(* Logix 5000 project; controller MVI56ESIE vendor 1 type 14 code 51 rev 15.5; software revision 15.02 *)

TASK MainTask (continuous, watchdog 500 ms) : MainProgram

MODULES
   Local : vendor 1 type 14 code 51 (ICP 0, rev 15.5)
      ENBT : 1756-ENBT (Ethernet 105.102.0.13, ICP 6, rev 4.3)
      MVI56ESIE : vendor 1 type 0 code 15 (ICP 1, rev 1.1, Output RPI 5 ms)
END_MODULES

TYPE SIEBLOCKSTATS :   // This object is used to store the block transfer statistics for the MVI56E-SIE module.
STRUCT
   Read : INT;   // Total number of read block transfers
   Write : INT;   // Total number of write block transfers
   Parse : INT;   // Total number of blocks parsed
   Reserved : INT;   // Used internally for future use
   Cmd : INT;   // Total number of command blocks received
   Err : INT;   // Total number of block transfer errors
END_STRUCT
END_TYPE

TYPE SIECLIENTSTATS :   // This object is used to store the port statistics for an MVI56E-SIE port.
STRUCT
   CmdReq : INT;   // Total number of command list requests sent
   CmdResp : INT;   // Total number of command list responses received
   CmdErr : INT;   // Total number of command list errors
   Requests : INT;   // Total number of requests for port
   Responses : INT;   // Total number of responses for port
   ErrSent : INT;   // Total number of errors sent
   ErrRec : INT;   // Total number of errors received
   CfgErrWord : INT;   // Configuration Error Word
   CurErr : INT;   // Current Error code
   LastErr : INT;   // Last recorded error code
END_STRUCT
END_TYPE

TYPE SIECMDCONTROL :   // MVI56E-SIE Command Control
STRUCT
   ClientID : INT;   // Block5000 Client Identification by Index number 0 to 19
   CMDqty : INT;   // Block5000 command quantity
   CmdIndex : INT[16];   // Contains index in the command list for the 1st command to be entered into Command queue
   WriteCmdBits : INT[20];   // Command Bit control ClientID(0 to 19)
END_STRUCT
END_TYPE

TYPE SIECONTROL :   // Values used by program for data transfer operation between the module and the processor.
STRUCT
   BootTimer : TIMER;   // Timer used to clear both cold and warm boot requests
   ColdBoot : BOOL;   // Hardware reset of the Module
   WarmBoot : BOOL;   // Configuration data reset in the Module.
   ResetStatus : BOOL;   // Resets module status
   CmdID : INT;   // Command ID from 1 to 16
   CmdControl : SIECMDCONTROL;   // Holds Command Control statistics
   CmdControlPending : BOOL;   // Halts rung until Module is ready.
   CmdControlTrigger : BOOL;   // Command Control Trigger
   IPAddress : SIEIPADDRESS;   // Getting and Setting IP address to and from Module
END_STRUCT
END_TYPE

TYPE SIEDATA :   // Contains Read Data (data read from the module to the processor) and Write Data (data written from the processor to the module)
STRUCT
   ReadData : INT[600];   // Data read from module. Set array equal to the size set in the Configuration file.
   WriteData : INT[600];   // Data to write to module. Set array equal to the size set in the Configuration file.
END_STRUCT
END_TYPE

TYPE SIEINITOUTDATA :   // Used to bring the Module into a known state after a restart operation.
STRUCT
   InitOutBlkIDLim : INT;   // Block Index Limit for ReadData size of the array
END_STRUCT
END_TYPE

TYPE SIEIPADDRESS :   // Data structure to get and set the IP address of the module.
STRUCT
   IPGetTrigger : BOOL;   // Gets IP Address
   IPReceived : INT[4];   // IP address received.
   IPSetTrigger : BOOL;   // Sets IP Address
   IPRequested : INT[4];   // IP address set.
END_STRUCT
END_TYPE

TYPE SIEMODULEDEF :   // This defines the whole module which includes all tags used in the program
STRUCT
   DATA : SIEDATA;   // Data read from module
   CONTROL : SIECONTROL;   // Client ,Server Status and blocks status
   STATUS : SIESTATUS;   // SIE Module control
   UTIL : SIEUTIL;   // Block statistics
END_STRUCT
END_TYPE

TYPE SIESTATUS :   // This status data is returned on each read block and can be used to detect proper module operation.
STRUCT
   PassCnt : INT;   // Program cycle counter
   ProductVersion : INT;   // This is used to pass the product version to the processor
   ProductCode : INT[2];   // This is used to pass the product Code to the processor
   BlockStats : SIEBLOCKSTATS;   // Block transfer statistics
   CmdBits : INT[20];   // Commands bits array to be used for 30 clients
   ClientStatsTrigger : BOOL;   // Get Client Status
   ClientID : INT;   // Client ID to get Status From
   ClientStatus : SIECLIENTSTATS[20];   // Client status data
   CmdErrorList : INT[16];   // Command Error List
END_STRUCT
END_TYPE

TYPE SIEUTIL :   // Values used by program for data transfer operation between the module and the processor.
STRUCT
   LastRead : INT;   // Index of last read block
   LastWrite : INT;   // Index of last write block
   BlockIndex : INT;   // Computed block offset for data table
   StatusIndex : INT;   // Computed block offset for status data
   ReadDataSizeGet : INT;   // Gets ReadData Array Length.
   WriteDataSizeGet : INT;   // Gets WriteData Array Length.
   ReadDataBlkCount : INT;   // Holds the value of the Block Counts of the Read Data Array.
   WriteDataBlkCount : INT;   // Holds the value of the Block Counts of the Write Data Array.
   RBTSremainder : INT;   // Holds remainder calculation value from the read array.
   WBTSremainder : INT;   // Holds remainder calculation value from the write array.
   IPsetPending : BOOL;   // Allows Setting module IP address
   IPgetPending : BOOL;   // Allows Getting module IP address
   InitOutputData : SIEINITOUTDATA;
   CheckInitialization : BOOL;   // Check Initialization trigger
   StatusSeqIndex : INT;   // Computed block offset for status data
END_STRUCT
END_TYPE

VAR_GLOBAL   (* controller tags *)
   MJFAULTS : DINT[12];
   SIE : SIEMODULEDEF;
END_VAR

PROGRAM MainProgram   (* main routine MainRoutine *)

ROUTINE MainRoutine   (* ladder *)
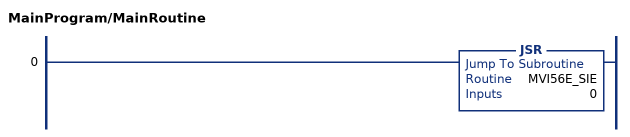
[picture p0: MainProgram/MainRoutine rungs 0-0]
   0: JSR(MVI56E_SIE,0);
END_ROUTINE

ROUTINE MVI56E_SIE   (* ladder *)
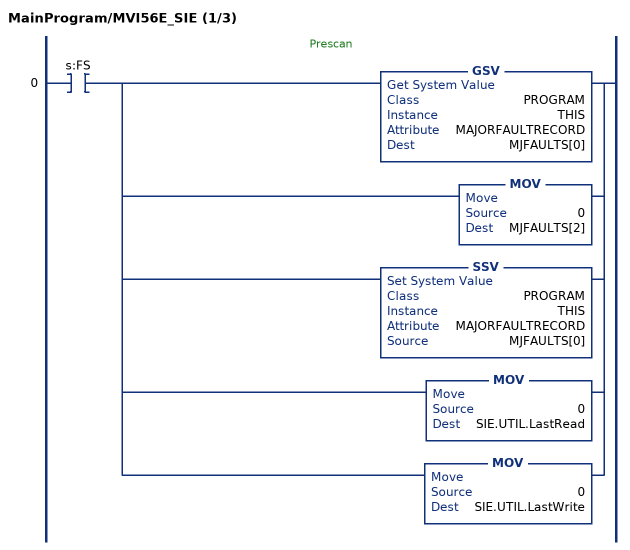
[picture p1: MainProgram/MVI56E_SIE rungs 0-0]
   // Prescan
   0: XIC(s:FS)[[GSV(PROGRAM,THIS,MAJORFAULTRECORD,MJFAULTS[0]) ,MOV(0,MJFAULTS[2]) ,SSV(PROGRAM,THIS,MAJORFAULTRECORD,MJFAULTS[0]) ] ,[MOV(0,SIE.UTIL.LastRead) ,MOV(0,SIE.UTIL.LastWrite) ] ];
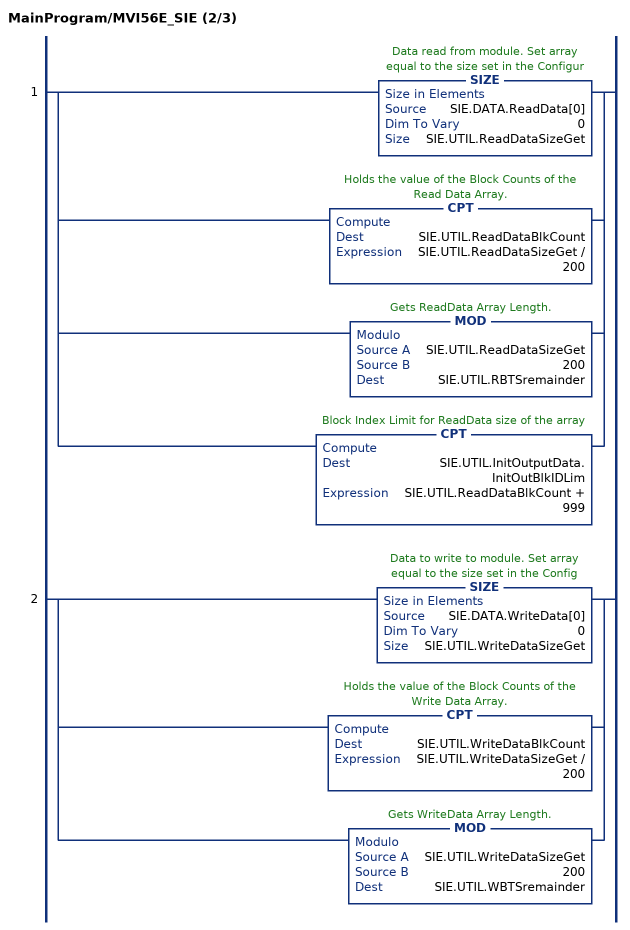
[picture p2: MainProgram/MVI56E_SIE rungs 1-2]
   1: [SIZE(SIE.DATA.ReadData[0],0,SIE.UTIL.ReadDataSizeGet) ,CPT(SIE.UTIL.ReadDataBlkCount,SIE.UTIL.ReadDataSizeGet / 200) ,MOD(SIE.UTIL.ReadDataSizeGet,200,SIE.UTIL.RBTSremainder) ,CPT(SIE.UTIL.InitOutputData.InitOutBlkIDLim,SIE.UTIL.ReadDataBlkCount + 999) ];
   2: [SIZE(SIE.DATA.WriteData[0],0,SIE.UTIL.WriteDataSizeGet) ,CPT(SIE.UTIL.WriteDataBlkCount,SIE.UTIL.WriteDataSizeGet / 200) ,MOD(SIE.UTIL.WriteDataSizeGet,200,SIE.UTIL.WBTSremainder) ];
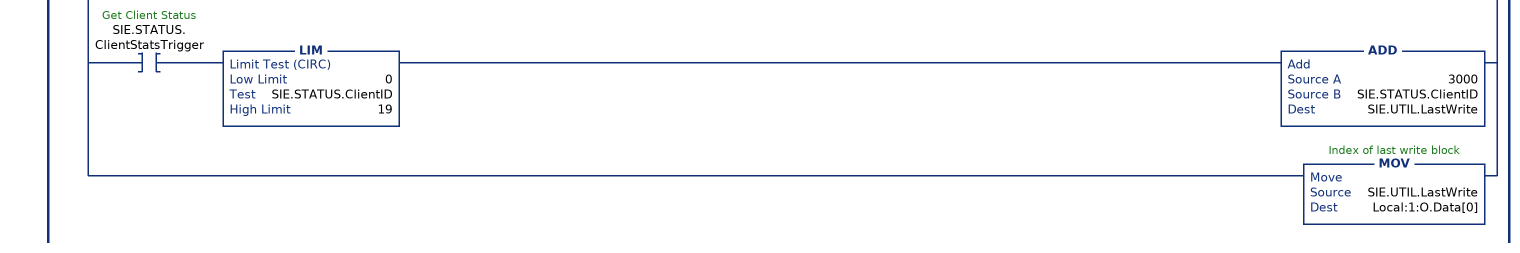
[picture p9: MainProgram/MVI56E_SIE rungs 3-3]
   3: NEQ(Local:1:I.Data[249],SIE.UTIL.LastRead)[MOV(Local:1:I.Data[249],SIE.UTIL.LastRead) ,GEQ(SIE.UTIL.LastRead,1) [LEQ(SIE.UTIL.LastRead,SIE.UTIL.ReadDataBlkCount) [CPT(SIE.UTIL.BlockIndex,(SIE.UTIL.LastRead-1)*200) ,COP(Local:1:I.Data[2],SIE.DATA.ReadData[SIE.UTIL.BlockIndex],200) ,COP(Local:1:I.Data[202],SIE.STATUS.PassCnt,1) ,COP(Local:1:I.Data[203],SIE.STATUS.BlockStats.Read,6) ,COP(Local:1:I.Data[209],SIE.STATUS.CmdBits[0],20) ,COP(Local:1:I.Data[229],SIE.STATUS.ProductCode[0],2) ,COP(Local:1:I.Data[231],SIE.STATUS.ProductVersion,1) ] ,CMP(SIE.UTIL.LastRead - SIE.UTIL.ReadDataBlkCount = 1) GRT(SIE.UTIL.RBTSremainder,0) [CPT(SIE.UTIL.BlockIndex,(SIE.UTIL.LastRead - 1) * 200) ,COP(Local:1:I.Data[2],SIE.DATA.ReadData[SIE.UTIL.BlockIndex],SIE.UTIL.RBTSremainder) ,COP(Local:1:I.Data[202],SIE.STATUS.PassCnt,1) ,COP(Local:1:I.Data[203],SIE.STATUS.BlockStats.Read,6) ,COP(Local:1:I.Data[209],SIE.STATUS.CmdBits[0],20) ,COP(Local:1:I.Data[229],SIE.STATUS.ProductCode[0],2) ,COP(Local:1:I.Data[231],SIE.STATUS.ProductVersion,1) ] ] ,LIM(3000,SIE.UTIL.LastRead,3029) [CPT(SIE.UTIL.StatusIndex,SIE.UTIL.LastRead-3000) ,COP(Local:1:I.Data[3],SIE.STATUS.ClientStatus[SIE.UTIL.StatusIndex].CmdReq,10) ,COP(Local:1:I.Data[13],SIE.STATUS.CmdErrorList[0],16) ,OTU(SIE.STATUS.ClientStatsTrigger) ] ,EQU(SIE.UTIL.LastRead,9990) [COP(Local:1:I.Data[2],SIE.CONTROL.IPAddress.IPRequested[0],4) ,OTU(SIE.UTIL.IPsetPending) ] ,EQU(SIE.UTIL.LastRead,9991) [COP(Local:1:I.Data[2],SIE.CONTROL.IPAddress.IPReceived[0],4) ,OTU(SIE.UTIL.IPgetPending) ] ,XIC(SIE.CONTROL.CmdControlTrigger) LIM(5001,SIE.UTIL.LastRead,5016) LIM(1,Local:1:I.Data[2],16) OTU(SIE.CONTROL.CmdControlTrigger) ,MOV(Local:1:I.Data[1],SIE.UTIL.LastWrite) ,XIC(SIE.CONTROL.WarmBoot) [MOV(9998,SIE.UTIL.LastWrite) ,OTU(SIE.CONTROL.WarmBoot) ] ,XIC(SIE.CONTROL.ColdBoot) [MOV(9999,SIE.UTIL.LastWrite) ,OTU(SIE.CONTROL.ColdBoot) ] ,XIC(SIE.CONTROL.ResetStatus) [MOV(9997,SIE.UTIL.LastWrite) ,OTU(SIE.CONTROL.ResetStatus) ] ,XIC(SIE.CONTROL.IPAddress.IPSetTrigger) XIO(SIE.UTIL.IPsetPending) [COP(SIE.CONTROL.IPAddress.IPRequested[0],Local:1:O.Data[1],4) ,MOV(9990,SIE.UTIL.LastWrite) ,OTU(SIE.CONTROL.IPAddress.IPSetTrigger) ,OTL(SIE.UTIL.IPsetPending) ] ,XIC(SIE.CONTROL.IPAddress.IPGetTrigger) XIO(SIE.UTIL.IPgetPending) [MOV(9991,SIE.UTIL.LastWrite) ,OTU(SIE.CONTROL.IPAddress.IPGetTrigger) ,OTL(SIE.UTIL.IPgetPending) ] ,XIC(SIE.CONTROL.CmdControlTrigger) LIM(1,SIE.CONTROL.CmdID,16) [LIM(0,SIE.CONTROL.CmdControl.ClientID,19) MOV(SIE.CONTROL.CmdControl.ClientID,Local:1:O.Data[1]) ,COP(SIE.CONTROL.CmdControl.CmdIndex[0],Local:1:O.Data[2],16) ,ADD(5000,SIE.CONTROL.CmdID,SIE.UTIL.LastWrite) ] ,GEQ(SIE.UTIL.LastWrite,1) [LEQ(SIE.UTIL.LastWrite,SIE.UTIL.WriteDataBlkCount) [CPT(SIE.UTIL.BlockIndex,(SIE.UTIL.LastWrite-1)*200) ,COP(SIE.DATA.WriteData[SIE.UTIL.BlockIndex],Local:1:O.Data[1],200) ,COP(SIE.CONTROL.CmdControl.WriteCmdBits[0],Local:1:O.Data[201],20) ] ,CMP(SIE.UTIL.LastWrite - SIE.UTIL.WriteDataBlkCount = 1) GRT(SIE.UTIL.WBTSremainder,0) [CPT(SIE.UTIL.BlockIndex,(SIE.UTIL.LastWrite - 1) * 200) ,COP(SIE.DATA.WriteData[SIE.UTIL.BlockIndex],Local:1:O.Data[1],SIE.UTIL.WBTSremainder) ,COP(SIE.CONTROL.CmdControl.WriteCmdBits[0],Local:1:O.Data[201],20) ] ] ,LIM(1000,SIE.UTIL.LastWrite,1024) LEQ(SIE.UTIL.LastWrite,SIE.UTIL.InitOutputData.InitOutBlkIDLim) [CPT(SIE.UTIL.BlockIndex,(SIE.UTIL.LastWrite-1000)*200) ,COP(SIE.DATA.ReadData[SIE.UTIL.BlockIndex],Local:1:O.Data[1],200) ] ,[EQU(-1,SIE.UTIL.LastWrite) ,EQU(0,SIE.UTIL.LastWrite) ] [[EQU(SIE.STATUS.ProductCode[1],13637) GEQ(SIE.STATUS.ProductVersion,204) ,EQU(SIE.STATUS.ProductCode[1],13635) GEQ(SIE.STATUS.ProductVersion,113) ] [GEQ(SIE.UTIL.WriteDataSizeGet,200) COP(SIE.DATA.WriteData[0],Local:1:O.Data[1],200) ,LES(SIE.UTIL.WriteDataSizeGet,200) COP(SIE.DATA.WriteData[0],Local:1:O.Data[1],SIE.UTIL.WBTSremainder) ] ,COP(SIE.CONTROL.CmdControl.WriteCmdBits[0],Local:1:O.Data[201],20) ] ,XIC(SIE.STATUS.ClientStatsTrigger) LIM(0,SIE.STATUS.ClientID,19) ADD(3000,SIE.STATUS.ClientID,SIE.UTIL.LastWrite) ,MOV(SIE.UTIL.LastWrite,Local:1:O.Data[0]) ];
END_ROUTINE
END_PROGRAM
